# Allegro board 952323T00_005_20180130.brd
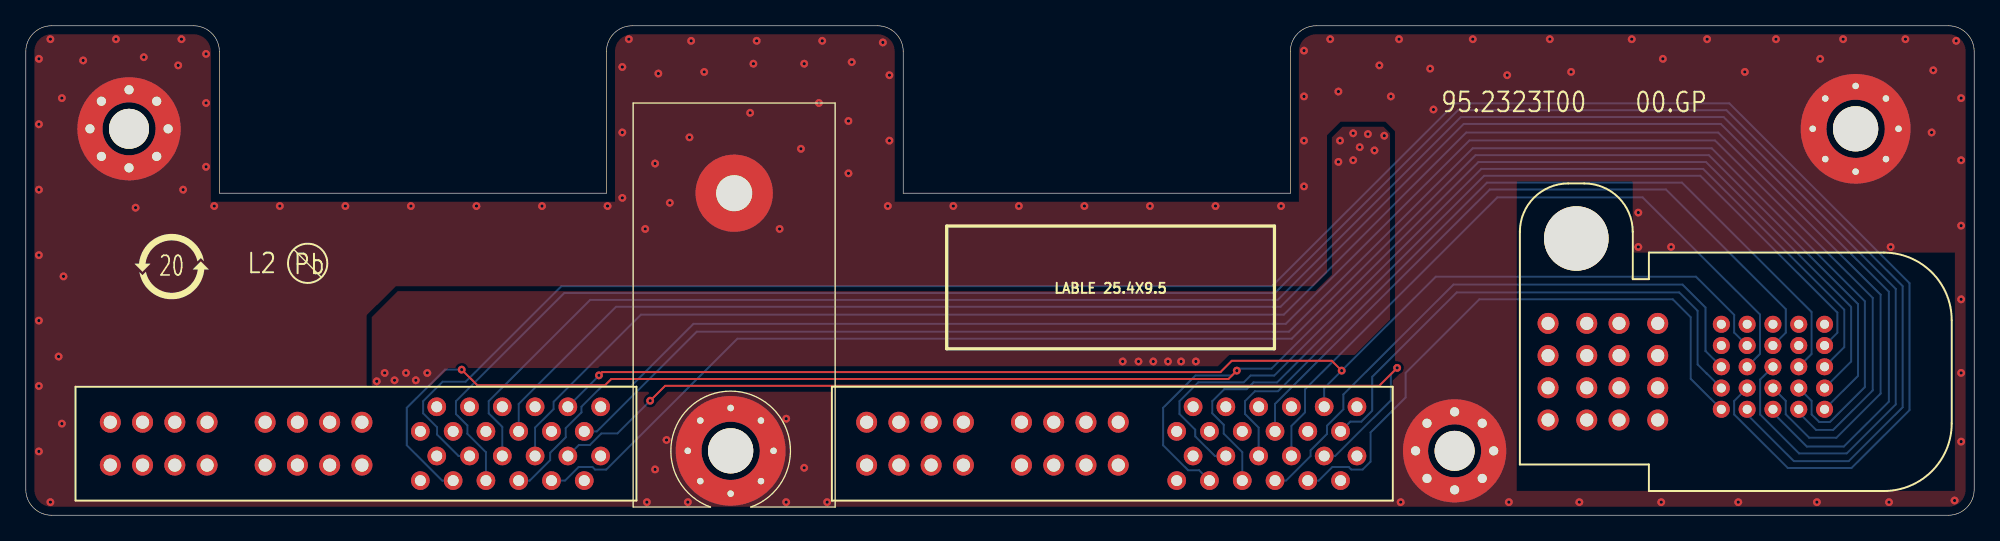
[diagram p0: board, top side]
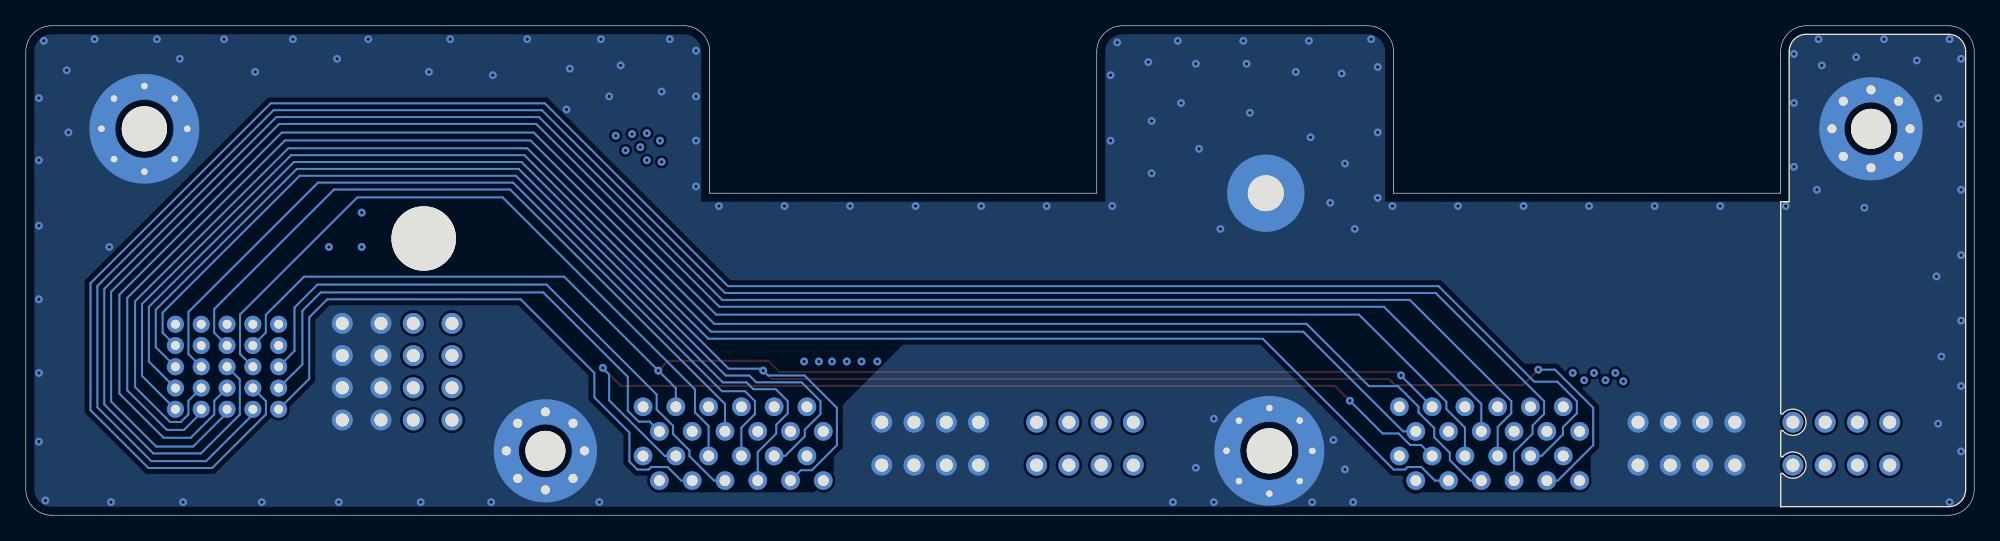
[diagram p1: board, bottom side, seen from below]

Outline 151 x 38 mm; copper layers: TOP, G02, P03, P04, G05, BOTTOM. Coordinates in mm from the lower left corner of the outline.
Outline path: 0,36 0,2 arc(0.59,0.59) 2,0 149,0 arc(150.41,0.59) 151,2 151,36 arc(150.41,37.41) 149,38 100,38 arc(98.59,37.41) 98,36 98,25 68,25 68,36 arc(67.41,37.41) 66,38 47,38 arc(45.59,37.41) 45,36 45,25 15,25 15,36 arc(14.41,37.41) 13,38 2,38 arc(0.59,37.41) 0,36

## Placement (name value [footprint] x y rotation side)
CN1  46562-1044  [CN-D32_96X23_37-41SK-TEMP]  132.52 11.13 0 top
CN2  46114-4241  [CN-D42_96X8_33-40-TEMP]  25.59 5.55 90 top
CN3  46114-4241  [CN-D42_96X8_33-40-TEMP]  84.21 5.55 90 top
H1  Hole-3.5/8.5mm  [GMTH138R335]  141.81 30 0 top
H2  Hole-2.8/6.0mm  [MPTH110R236]  54.9 25 0 top
H3  Hole-3.5/8.5mm  [GMTH138R335]  54.62 5 0 top
H4  Hole-3.1/8mm  [GMTH122R315]  110.73 5 0 top
H5  Hole-3.1/8mm  [GMTH122R315]  8 30 0 top
NOREF  -  []  20.32 19.56 0 top
NOREF#2  -  []  11.3 19.3 0 top
NOREF#3  -  []  75.5 0 90 top
NOREF#4  -  []  0 36 0 top
NOREF#5  -  []  0 0 0 top
NOREF#6  -  []  155.45 68.48 0 top
NOREF#7  -  []  155.32 73.82 0 top
NOREF#8  -  []  8 30 0 top
NOREF#9  -  []  155.83 78.26 0 top

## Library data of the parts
CN1 = 46437-1044_2
CN2 CN3 = 45984-4143_PWR_Connector_2
H1 H3-H5 = Hole-MTG-8VIA
H2 = TOOLING HOLE-1PIN-MPTH

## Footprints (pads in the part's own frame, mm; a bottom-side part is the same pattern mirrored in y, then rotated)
CN-D32_96X23_37-41SK-TEMP
  round 5 hole 5 unplated: (-12.36,10.35)
  round 1.321 hole 0.7: A1(6.88,-2.91) A2(4.88,-2.91) A3(2.88,-2.91) A4(0.88,-2.91) A5(-1.12,-2.91) B1(6.88,-1.26) B2(4.88,-1.26) B3(2.88,-1.26) B4(0.88,-1.26) B5(-1.12,-1.26) C1(6.88,0.39) C2(4.88,0.39) C3(2.88,0.39) C4(0.88,0.39) C5(-1.12,0.39) D1(6.88,2.04) D2(4.88,2.04) D3(2.88,2.04) D4(0.88,2.04) D5(-1.12,2.04) E1(6.88,3.69) E2(4.88,3.69) E3(2.88,3.69) E4(0.88,3.69) E5(-1.12,3.69)
  round 1.626 hole 1.02: P1_1(-6.05,-3.74) P1_2(-6.05,-1.24) P1_3(-6.05,1.26) P1_4(-6.05,3.76) P1_5(-9.05,-3.74) P1_6(-9.05,-1.24) P1_7(-9.05,1.26) P1_8(-9.05,3.76) P2_1(-11.55,-3.74) P2_2(-11.55,-1.24) P2_3(-11.55,1.26) P2_4(-11.55,3.76) P2_5(-14.55,-3.74) P2_6(-14.55,-1.24) P2_7(-14.55,1.26) P2_8(-14.55,3.76)
CN-D42_96X8_33-40-TEMP
  round 1.448 hole 0.85: CKT1(2.865,-18.957) CKT2(0.955,-17.687) CKT3(2.865,-16.417) CKT4(0.955,-15.147) CKT5(2.865,-13.877) CKT6(0.955,-12.607) CKT7(2.865,-11.337) CKT8(0.955,-10.067) CKT9(2.865,-8.797) CKT10(0.955,-7.527) CKT11(2.865,-6.257) CKT12(0.955,-4.987) CKT13(-0.955,-18.957) CKT14(-2.865,-17.687) CKT15(-0.955,-16.417) CKT16(-2.865,-15.147) CKT17(-0.955,-13.877) CKT18(-2.865,-12.607) CKT19(-0.955,-11.337) CKT20(-2.865,-10.067) CKT21(-0.955,-8.797) CKT22(-2.865,-7.527) CKT23(-0.955,-6.257) CKT24(-2.865,-4.987)
  round 1.626 hole 1.02: P1A_1(1.665,7.044) P1A_2(1.665,4.544) P1A_3(1.665,2.043) P1A_4(1.665,-0.457) P1B_1(-1.665,7.044) P1B_2(-1.665,4.544) P1B_3(-1.665,2.043) P1B_4(-1.665,-0.457) P2A_1(1.665,19.044) P2A_2(1.665,16.544) P2A_3(1.665,14.043) P2A_4(1.665,11.543) P2B_1(-1.665,19.044) P2B_2(-1.665,16.544) P2B_3(-1.665,14.043) P2B_4(-1.665,11.543)
GMTH122R315
  round 3.099 hole 3.099 unplated: (0,0)
  round 1.016 hole 0.711: 1(3.029,0) 2(2.142,2.142) 3(0,3.029) 4(-2.142,2.142) 5(-3.029,0) 6(-2.142,-2.142) 7(0,-3.029) 8(2.142,-2.142)
GMTH138R335
  round 3.505 hole 3.505 unplated: (0,0)
  round 0.813 hole 0.508: 1(2.351,-2.351) 2(3.325,0) 3(2.351,2.351) 4(0,3.325) 5(-2.351,2.351) 6(-3.325,0) 7(-2.351,-2.351) 8(0,-3.325)
MPTH110R236
  round 5.994 hole 2.794: 1(0,0)

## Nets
+12VBUS: CN2.CKT15(+12VBUS) CN3.CKT15(+12VBUS)
GND: CN1.D2 CN1.D5 CN1.E4 CN1.E5 CN1.P1_1 CN1.P1_2 CN1.P1_3 CN1.P1_4 CN1.P1_5 CN1.P1_6 CN1.P1_7 CN1.P1_8 CN2.CKT14(+12VRS) CN2.P1A_1(GND#4) CN2.P1A_2(GND#5) CN2.P1A_3(GND#6) CN2.P1A_4(GND#7) CN2.P1B_1(GND#0) CN2.P1B_2(GND#1) CN2.P1B_3(GND#2) CN2.P1B_4(GND#3) CN3.CKT14(+12VRS) CN3.P1A_1(GND#4) CN3.P1A_2(GND#5) CN3.P1A_3(GND#6) CN3.P1A_4(GND#7) CN3.P1B_1(GND#0) CN3.P1B_2(GND#1) CN3.P1B_3(GND#2) CN3.P1B_4(GND#3) H1.1(GND1) H1.2(GND2) H1.3(GND3) H1.4(GND4) H1.5(GND5) H1.6(GND6) H1.7(GND7) H1.8(GND8) H2.1 H3.1(GND1) H3.2(GND2) H3.3(GND3) H3.4(GND4) H3.5(GND5) H3.6(GND6) H3.7(GND7) H3.8(GND8) H4.1(GND1) H4.2(GND2) H4.3(GND3) H4.4(GND4) H4.5(GND5) H4.6(GND6) H4.7(GND7) H4.8(GND8) H5.1(GND1) H5.2(GND2) H5.3(GND3) H5.4(GND4) H5.5(GND5) H5.6(GND6) H5.7(GND7) H5.8(GND8)
P5V_SB: CN1.E1 CN1.E2 CN1.E3 CN2.CKT11(5VSB#2) CN2.CKT12(5VSB#3) CN2.CKT23(5VSB#0) CN2.CKT24(5VSB#1) CN3.CKT11(5VSB#2) CN3.CKT12(5VSB#3) CN3.CKT23(5VSB#0) CN3.CKT24(5VSB#1)
P12V: CN1.P2_1 CN1.P2_2 CN1.P2_3 CN1.P2_4 CN1.P2_5 CN1.P2_6 CN1.P2_7 CN1.P2_8 CN2.CKT13(+12VS) CN2.P2A_1(12V#4) CN2.P2A_2(12V#5) CN2.P2A_3(12V#6) CN2.P2A_4(12V#7) CN2.P2B_1(12V#0) CN2.P2B_2(12V#1) CN2.P2B_3(12V#2) CN2.P2B_4(12V#3) CN3.CKT13(+12VS) CN3.P2A_1(12V#4) CN3.P2A_2(12V#5) CN3.P2A_3(12V#6) CN3.P2A_4(12V#7) CN3.P2B_1(12V#0) CN3.P2B_2(12V#1) CN3.P2B_3(12V#2) CN3.P2B_4(12V#3)
I2C0_PSU1_SCL: CN1.A2 CN2.CKT18(SCL)
I2C0_PSU1_SDA: CN1.B3 CN2.CKT17(SDA)
I2C0_PSU2_SCL: CN1.C5 CN3.CKT18(SCL)
I2C0_PSU2_SDA: CN1.C4 CN3.CKT17(SDA)
PSU1_ALRT_N: CN1.A1 CN2.CKT16(SMB_ALERT)
PSU1_EEPROM_WP: CN1.A3 CN2.CKT6(EEPROM_WP)
PSU1_PRSNT_IN_N: CN1.B2 CN2.CKT2(PRESENT)
PSU1_PSKILL: CN1.C3 CN2.CKT19(PS_KILL)
PSU1_PSON_N: CN1.A4 CN2.CKT20(PS_ON)
PSU1_PWRGD: CN1.B4 CN2.CKT21(PW_OK)
PSU2_ALRT_N: CN1.A5 CN3.CKT16(SMB_ALERT)
PSU2_EEPROM_WP: CN1.D3 CN3.CKT6(EEPROM_WP)
PSU2_PRSNT_IN_N: CN1.B5 CN3.CKT2(PRESENT)
PSU2_PSKILL: CN1.C2 CN3.CKT19(PS_KILL)
PSU2_PSON_N: CN1.D1 CN3.CKT20(PS_ON)
PSU2_PWRGD: CN1.C1 CN3.CKT21(PW_OK)
PSU_A0: CN1.D4 CN2.CKT3(A0) CN3.CKT3(A0)
PSU_A1: CN1.B1 CN2.CKT22(A1) CN3.CKT22(A1)

Pads without a net: CN2 CKT1 CKT4 CKT5 CKT7 CKT8 CKT9 CKT10; CN3 CKT1 CKT4 CKT5 CKT7 CKT8 CKT9 CKT10

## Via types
v1: diameter 0.61, hole 0.254, TOP to BOTTOM, 140 vias

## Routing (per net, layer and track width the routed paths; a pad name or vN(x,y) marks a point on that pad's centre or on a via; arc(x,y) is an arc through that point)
+12VBUS: length 76.8
  TOP w0.152: v1(106.28,11.44) 104.89,10.05 49.54,10.05 v1(48.39,8.89)
  BOTTOM w0.152: v1(106.28,11.44) 106.28,11.41 105.79,10.92 105.79,8.92 101.48,4.6 CN3.CKT15 ; v1(48.39,8.89) 45.85,6.35 44.61,6.35 43.72,5.46 42.87,5.46 CN2.CKT15
GND: length 125.4
  P03 w0.381: CN1.P1_1 125.05,5.97 115.89,5.97 112.27,9.59 89.73,9.59 87.84,7.7 87.84,4.03 85.55,1.74 64.36,1.74 63.92,2.19 61.34,4.76 61.34,7.05 58.87,9.53 51.56,9.53 44.73,2.69 CN2.CKT14
  P04 w0.381: CN1.P1_5 122.08,6 115.92,6 112.39,9.53 108.27,9.53 105.23,6.49 105.23,5.01 102.91,2.69 CN3.CKT14
  vias: v1(1.02,35.43) v1(1.02,30.35) v1(1.02,25.27) v1(1.02,20.19) v1(1.02,15.11) v1(1.02,10.03) v1(1.02,4.95) v1(1.91,36.96) v1(1.91,1.02) v1(2.54,12.32) v1(2.79,32.38) v1(2.79,7.11) v1(2.92,18.54) v1(4.45,35.31) v1(6.99,36.96) v1(8.51,23.88) v1(9.14,35.56) v1(11.81,34.92) v1(12.06,36.96) v1(12.19,25.27) v1(13.97,35.81) v1(13.97,32) v1(13.97,27.05) v1(14.61,24) v1(19.68,24) v1(24.77,24) v1(29.84,24) v1(34.92,24) v1(40.01,24) v1(45.09,24) v1(46.23,34.8) v1(46.23,29.72) v1(46.23,24.64) v1(46.74,36.96) v1(48.01,22.23) v1(48.13,1.02) v1(48.77,27.3) v1(48.77,3.56) v1(49.02,34.29) v1(49.66,5.84) v1(49.91,24.26) v1(51.31,1.02) v1(51.44,29.34) v1(51.56,36.83) v1(52.58,34.42) v1(56.13,31.24) v1(56.39,35.05) v1(56.64,36.83) v1(58.42,22.23) v1(58.93,7.49) v1(58.93,1.02) v1(60.07,28.45) v1(60.33,35.05) v1(60.33,3.68) v1(61.47,32) v1(61.72,36.83) v1(62.1,1.02) v1(63.75,30.61) v1(63.75,26.54) v1(64.01,35.18) v1(66.42,36.7) v1(66.8,24) v1(66.93,34.16) v1(66.93,29.08) v1(71.88,24) v1(76.96,24) v1(82.04,24) v1(87.12,24) v1(92.2,24) v1(97.28,24) v1(99.06,36.07) v1(99.06,32.51) v1(99.06,29.08) v1(99.06,25.53) v1(101.09,36.96) v1(101.73,32.89) v1(104.9,34.92) v1(105.79,32.51) v1(106.43,36.96) v1(106.55,1.02) v1(108.84,34.67) v1(109.09,31.5) v1(112.14,36.96) v1(114.81,34.16) v1(114.94,1.02) v1(118.11,36.96) v1(119.76,34.42) v1(120.4,1.02) v1(124.46,36.96) v1(124.97,23.5) v1(124.97,20.83) v1(126.75,1.02) v1(126.87,35.43) v1(127.51,20.83) v1(130.3,36.96) v1(132.72,1.02) v1(133.22,34.42) v1(135.64,36.96) v1(138.81,1.02) v1(139.06,35.43) v1(140.84,36.96) v1(144.4,1.02) v1(144.53,20.83) v1(145.67,36.96) v1(147.7,29.72) v1(147.83,34.54) v1(149.48,1.14) v1(149.61,36.83) v1(149.99,32.38) v1(149.99,27.56) v1(149.99,22.48) v1(149.99,16.76) v1(149.99,11.05) v1(149.99,5.71)
P5V_SB:
  vias: v1(27.2,10.4) v1(27.81,11.05) v1(28.57,10.48) v1(29.46,11.05) v1(30.23,10.48) v1(31.11,11.05) v1(85.01,11.94) v1(86.23,11.94) v1(87.38,11.94) v1(88.52,11.94) v1(89.53,11.94) v1(90.68,11.94) v1(101.73,27.43) v1(101.85,29.08) v1(102.87,29.65) v1(102.87,27.56) v1(103.38,28.57) v1(104.01,29.59) v1(104.52,28.32) v1(105.28,29.46)
P12V: length 106
  P03 w0.381: CN2.CKT13 45.56,4.6 51.25,10.29 59.18,10.29 62.1,7.37 62.1,5.08 64.68,2.51 85.24,2.51 87,4.26 87,7.93 89.41,10.35 112.59,10.35 115.57,7.37 117.94,7.37 CN1.P2_5 ; 117.98,7.38 117.96,7.37
  P04 w0.381: CN1.P2_5 117.96,7.38 115.61,7.38 112.58,10.41 108.08,10.41 103.16,5.5 CN3.CKT13
I2C0_PSU1_SCL: length 136.9
  BOTTOM w0.152: CN2.CKT18 39.05,2.69 40.64,4.28 40.64,4.84 41.84,6.05 41.84,6.76 43.06,7.98 43.06,8.42 44.66,10.02 46.91,10.02 51.74,14.86 97.64,14.86 111.88,29.1 130.91,29.1 143.14,16.87 143.14,9.7 140.07,6.62 138.74,6.62 137.4,7.96 CN1.A2
I2C0_PSU1_SDA: length 141.2
  BOTTOM w0.152: CN1.B3 136.39,8.88 136.39,7.83 138.21,6.02 140.32,6.02 143.75,9.44 143.75,17.12 131.16,29.71 111.63,29.71 97.5,15.58 47.67,15.58 40.9,8.81 40.9,8.24 39.47,6.8 CN2.CKT17
I2C0_PSU2_SCL: length 46.8
  BOTTOM w0.152: CN1.C5 130.18,12.75 130.18,12.75 130.18,16.13 128.39,17.91 110.64,17.91 102.11,9.37 102.11,8.22 100.84,6.95 100.84,6.31 99.57,5.04 99.57,4.6 97.67,2.69 CN3.CKT18
I2C0_PSU2_SDA: length 55.3
  BOTTOM w0.152: CN3.CKT17 98.08,6.93 99.14,7.98 99.14,9.77 114.04,24.68 125.3,24.68 134.4,15.58 134.4,12.52 CN1.C4
PSU1_ALRT_N: length 125.9
  BOTTOM w0.152: CN1.A1 141.99,10.82 141.99,16.4 130.44,27.96 112.36,27.96 98.11,13.7 55.14,13.7 44.99,3.55 44.11,3.55 43.91,3.74 42.84,3.74 41.79,2.69 CN2.CKT16
PSU1_EEPROM_WP: length 143
  BOTTOM w0.152: CN1.A3 135.4,7.96 138.03,5.33 140.9,5.33 144.39,8.82 144.39,17.35 131.36,30.38 111.44,30.38 97.24,16.18 45.74,16.18 38.2,8.64 CN2.CKT6
PSU1_PRSNT_IN_N: length 127.9
  BOTTOM w0.152: CN1.B2 138.4,8.88 138.4,7.83 138.99,7.23 139.81,7.23 142.53,9.95 142.53,16.62 130.66,28.49 112.14,28.49 97.9,14.25 52,14.25 44.26,6.51 CN2.CKT2
PSU1_PSKILL: length 154.8
  BOTTOM w0.152: CN2.CKT19 36.93,6.86 35.88,7.91 35.88,8.86 43.74,16.72 97.02,16.72 111.22,30.91 131.58,30.91 144.92,17.57 144.92,8.6 141.12,4.8 137.43,4.8 134.41,7.81 134.41,10.53 CN1.C3
PSU1_PSON_N: length 159.4
  BOTTOM w0.152: CN2.CKT20 35.66,4.89 34.22,6.33 34.22,6.97 33.34,7.86 33.34,8.86 41.73,17.25 96.8,17.25 111,31.44 131.8,31.44 145.45,17.79 145.45,8.38 141.27,4.2 137.02,4.2 133.4,7.82 CN1.A4
PSU1_PWRGD: length 166.3
  BOTTOM w0.152: CN1.B4 132.39,8.87 132.39,7.83 136.55,3.67 141.49,3.67 145.99,8.16 145.99,18.01 132.02,31.98 110.78,31.98 96.58,17.79 41.51,17.79 34.09,10.37 32.31,10.37 30.8,8.86 30.8,7.91 31.87,6.83 31.87,6.26 33.54,4.6 CN2.CKT21
PSU2_ALRT_N: length 46.8
  BOTTOM w0.152: CN1.A5 130.59,9.04 130.58,9.04 129.03,10.59 129.03,15.37 127.63,16.76 112.65,16.76 106.93,11.05 106.93,9.14 104.22,6.43 104.22,4.16 103.6,3.55 102.73,3.55 102.53,3.74 101.26,3.74 100.21,2.69 CN3.CKT16
PSU2_EEPROM_WP: length 55.7
  BOTTOM w0.152: CN3.CKT6 96.81,8.64 113.46,25.29 127.11,25.29 136.4,16 136.4,14.17 CN1.D3
PSU2_PRSNT_IN_N: length 41
  BOTTOM w0.152: CN3.CKT2 102.65,7.26 103.5,7.26 104.35,8.11 104.35,10.75 110.9,17.3 128.14,17.3 129.57,15.87 129.57,11.71 130.26,11.01 130.27,11.01 CN1.B5
PSU2_PSKILL: length 64.4
  BOTTOM w0.152: CN1.C2 138.39,12.52 138.39,15.78 128.35,25.82 113.24,25.82 97.05,9.63 95.26,9.63 94.49,8.86 94.49,7.86 95.54,6.8 CN3.CKT19
PSU2_PSON_N: length 70.2
  BOTTOM w0.152: CN1.D1 140.39,14.17 140.39,15.73 129.77,26.36 113.02,26.36 96.98,10.31 95.14,10.31 94.61,9.78 92.88,9.78 91.95,8.86 91.95,7.91 92.84,7.02 92.84,6.34 94.27,4.9 CN3.CKT20
PSU2_PWRGD: length 74.8
  BOTTOM w0.152: CN1.C1 140.93,13.05 140.93,15.96 129.99,26.89 112.8,26.89 96.76,10.85 94.92,10.85 94.39,10.32 90.87,10.32 89.41,8.86 89.41,7.86 90.63,6.64 90.63,6.12 92.15,4.6 CN3.CKT21
PSU_A0: length 102.6
  TOP w0.152: v1(44.42,10.86) 44.67,11.11 91,11.11 92.58,11.11 93.46,11.99 101.22,11.99 v1(101.98,11.23)
  BOTTOM w0.152: v1(44.42,10.86) 44.42,10.83 CN2.CKT3 ; CN3.CKT3 100.62,9.87 v1(101.98,11.23) 109.27,18.52 129.44,18.52 132.4,15.56 132.4,14.18 CN1.D4
PSU_A1: length 154.8
  TOP w0.152: v1(93.85,11.23) 93.21,10.58 45.38,10.58 44.89,10.1 34.99,10.1 v1(33.78,11.3)
  BOTTOM w0.152: CN2.CKT22 32.27,2.69 29.53,5.43 29.53,8.34 32.49,11.3 v1(33.78,11.3) ; CN1.B1 141.46,11.93 141.46,16.18 130.22,27.42 112.58,27.42 96.54,11.38 94.01,11.38 v1(93.85,11.23) 93.48,10.85 90.65,10.85 88.14,8.34 88.14,5.43 90.08,3.5 90.93,3.5 CN3.CKT22

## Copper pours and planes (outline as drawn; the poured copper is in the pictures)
GND on TOP (solid shape): outline of 244 points within 4,26 12,34
GND on TOP (solid shape): outline of 244 points within 106.73,1 114.73,9
GND on TOP (solid shape): outline of 254 points within 50.37,0.75 58.88,9.25
GND on TOP (solid shape): outline of 254 points within 137.55,25.75 146.06,34.25
GND on BOTTOM (solid shape): outline of 244 points within 4,26 12,34
GND on BOTTOM (solid shape): outline of 244 points within 106.73,1 114.73,9
GND on BOTTOM (solid shape): outline of 254 points within 50.37,0.75 58.88,9.25
GND on BOTTOM (solid shape): outline of 254 points within 137.55,25.75 146.06,34.25
P5V_SB on TOP: 27.05,9.91 26.8,10.16 26.8,15.37 28.83,17.4 99.95,17.4 101.22,18.67 101.22,29.34 102.04,30.16 105.22,30.16 105.73,29.65 105.73,15.18 103,12.45 101.09,12.45 100.58,11.94 101.09,11.43 32.77,11.43 31.24,9.91
P5V_SB on P03: 140.72,14.61 140.34,14.22 134.75,14.22 134.37,14.61 134.37,16 125.35,25.02 101.98,25.02 101.22,25.78 101.22,29.21 102.17,30.16 127.32,30.16 140.72,16.76
P5V_SB on P04: 28.96,1.91 31.68,1.91 33.21,3.43 33.21,12.06 32.76,12.51 26.67,12.51 26.22,12.06 26.22,9.53 27.69,8.06 27.69,3.17
P5V_SB on P04: 90.74,1.84 91.95,3.05 91.95,11.18 90.81,12.32 84.71,12.32 84.33,11.94 84.33,10.54 86.61,8.26 86.61,2.6 87.38,1.84
P12V on P03: 115.06,23.37 117.14,21.29 118.02,19.33 119.98,18.45 122.17,16.26 122.17,7.11 121.54,6.48 117.47,6.48 111.51,12.45 77.98,12.45 74.3,8.76 74.3,4.06 73.15,2.92 65.02,2.92 63.63,4.32 63.63,8.13 60.83,10.92 48.26,10.92 46.74,9.4 34.42,9.4 33.91,9.91 33.91,11.05 33.02,11.94 26.54,11.94 25.78,11.18 25.78,10.03 25.15,9.4 17.14,9.4 16.64,8.89 16.64,3.3 14.99,1.65 5.46,1.65 4.06,3.05 4.06,16.38 10.41,22.73 45.85,22.73 47.12,21.46 58.8,21.46 60.71,23.37
P12V on P04: 115.06,23.37 117.14,21.29 118.02,19.33 119.98,18.45 122.17,16.26 122.17,7.11 121.54,6.48 117.47,6.48 111.25,12.7 78.23,12.7 74.3,8.76 74.3,4.06 73.15,2.92 65.02,2.92 63.63,4.32 63.63,7.87 62.1,9.4 34.42,9.4 33.91,9.91 33.91,11.05 33.02,11.94 26.54,11.94 25.91,11.3 25.91,10.16 25.15,9.4 17.14,9.4 16.64,8.89 16.64,3.3 14.99,1.65 5.46,1.65 4.06,3.05 4.06,16.38 10.41,22.73 45.85,22.73 47.12,21.46 58.8,21.46 60.71,23.37

Small or netless copper shapes (teardrops, artwork), in the pictures only: 1 on TOP, 1 on BOTTOM, 1 on G02, 1 on P03, 1 on P04, 1 on G05

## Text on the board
Ref Des/Silkscreen Top: LABLE 25.4X9.5 | 95.2323T00 | 00.GP
PAGE_OUTLINE: 2018.01.30 | UNLESS OTHERWISE SPECIFIED | DIMENSIONS ARE IN INCHES | TOLERANCES ON; | 2 PL DECIMALS +/- .010 | 3 PL DECIMALS +/- .005 | ANGLES +/- 5 | FRACTIONS + | ISSUED | CAD | ENGRG | SIGNATURES | Jenna | Mars | DATE | SCALE | SIZE | FSCM NO | DWG NO | SHEET | REV | DESCRIPTION | REVISIONS | APPROVED | 95.2323T00 | D | C | B | A | 7 | 6 | 5 | 4 | 3 | 2 | 1 | UfiSpace
BODY_CENTER: 14.PCB VENDOR MUST BE UL QUALIFIED | 10.ALL COPPER FEATURES ON THE BOARD ARE TO BE FINISHED WITH OSP COAT. | 11.THIS IS A 6 LAYER BOARD. VENDER TO PROVIDE BOARD STACK-UP FOR IMPEDANCE | APPROVAL PRIOR TO BOARD FABRICATION.STACK-UP AND IMPEDANCE TO INCLUDE COPPER | PLANTING THICKNESS ON OUTER LAYERS. | 12.ADD SQUARE SHAPED THIEVING PADS IN 50MILSX50MILS DIMENSION ON ALL THE SIGNAL | 13.NO THIEVING PERMITTED ON ANY ELECTRICAL LAYERS IN THIS AREA. | 15.BOARD MUST BE IDENTIFIED WITH APPROPRIATE VENDOR UL IDENTIFACTION MARK,DATE CODE. | 16.PCB MATERIAL UL FLAMMABILITY RATING(94V-0 MINIMUM) | OVER BARE COPPER PRIOR TO ANY PLATING FINISH PROCESSES | 2. ALL FINISHED BOARDS TO BE ELECTRICALLY TESTED. | 3. SILKSCREEN TO BE WHITE. NON-CONDUCTIVE , EPOXY INK OR EQUIVALENT. | 4. SOLDERMASK GREEN LIQUID PHOTO-IMAGABLE SMOBC SOLDERMASK TO BE APPLIED | 5. BOARD THICKNESS IS 0.0774" +/- 10% | 6 .NON-FUNCTIONAL PADS ON INTERNAL LAYERS MAY BE OMITTED. | 7 .TEARDROP TRACE ENTRY TO VIAS ON INTERNAL LAYERS, PROVIDED DRC RULES ARE MET. | 8 .ACCEPTABLE MINIMUM ANNULAR RING FOR VIA IS 0.001". | 9 .THIS IS A CONTROLLED IMPEDANCE BOARD. CONTROLS ARE AS FOLLOWS: | 1. MATERIAL:FR-4 OR EQUIVALENT. THE USE OF SINGLE PLY CONSTRUCION IS OPTIONAL | NOTES: (UNLESS OTHERWISE SPECIFIED) | LAYERS. THESE SHOULD BE 200 MILS AWAY FROM ALL FUNCTIONAL COPPER. DO NOT ADD | THIEVING ON PLANE LAYERS. | IMPEDANCE SHALL BE 50 OHMS +/-10% ON OUTER LAYERS WITH 0.006 INCH TRACES.
User.9: 1     2 | TOP SIDE SOLDER PAST
User.10: 2     2 | BOTTM SIDE SOLDER PAST
User.11: 9     10 | TOP SIDE SILK SCREEN
User.12: 10     10 | BOTTOM SIDE SILK SCREEN
User.13: 7     10 | TOP SIDE SOLDERMASK
User.14: 8     10 | BOTTOM SIDE SOLDERMASK
User.15: 1 TO 1 | FABRICATION
User.16: 1 TO 2 | ASSY_TOP
User.17: 2 TO 2 | ASSY_BOT | BOTTOM SIDE VIEW
User.19: 0.0774 | +/-10% | FOIL+Plating- 2.0 OZ | CORE - 0.016 1/2 | CORE - 0.016 2/1 | PRE-PREG - 0.0037 | PRE-PREG - 0.026 | NOTE: COPPER THICKNESS IS INCLUDED IN THE OVER ALL | BOARD THICKNESS SPECIFICATION | COMPONENT SIDE -LAYER1 | GND   PLANE    -LAYER2 | POWER 1 PLANE  -LAYER3 | POWER 2 PLANE  -LAYER4 | GND   PLANE    -LAYER5 | SOLDER SIDE    -LAYER6
User.20: 1     10 | 1   COMPONENT SIDE
User.21: 2    GND PLANE 1 | 2     10
User.22: 3    INNER SIGNAL 1 | 3     10
User.23: 4    INNER SIGNAL 2 | 4     10
User.24: 5   POWER PLANE 2 | 5     10
User.25: 6  BOTTOM SIDE | 6     10
User.26: 2018.01.30 | LAYER | PROJECT | P/N:308.03055.005 | VER:005 | H/W | CAD | SIGNATURES | SHEET    OF | Mars | Jenna | DATA | 95.2323T00 | GERBER | UfiSpace
User.27: TOP SIDE SOLDER PAST | & SILK | 1     2
User.28: BOTTOM SIDE SOLDER PAST | & SILK | 2     2
User.29: 2018.01.30 | SHEET | DWG NO | FSCM NO | SIZE | SCALE | DATE | Jenna | Mars | SIGNATURES | CAD | ENGRG | ISSUED | UNLESS OTHERWISE SPECIFIED | DIMENSIONS ARE IN INCHES | TOLERANCES ON; | 2 PL DECIMALS +/- .010 | 3 PL DECIMALS +/- .005 | ANGLES +/- 5 | FRACTIONS + | APPROVED | REVISIONS | DESCRIPTION | REV | D | 95.2323T00 | B | C | A | 1 | 2 | 3 | 4 | 5 | 6 | 7 | UfiSpace
User.30: 2 OF 2 | PANEL DRAWING
User.36: FIGURE | FHS | 10.0 | 20.0 | 27.56 | 28.0 | 33.46 | 40.16 | 110.0 | 122.0 | 138.0 | 196.85 | DRILL CHART: TOP to BOTTOM | ALL UNITS ARE IN MILS | TOLERANCE | +2.0/-7.0 | +3.0/-3.0 | +2.0/-2.0 | +4.0/-4.0 | PLATED | NON-PLATED | QTY | 140 | 16 | 25 | 48 | 1 | 2
